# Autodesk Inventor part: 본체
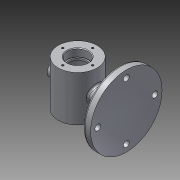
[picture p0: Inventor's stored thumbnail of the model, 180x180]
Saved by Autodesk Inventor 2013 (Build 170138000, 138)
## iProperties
Created: 2018-12
Part Number: 본체
Material: 알루미늄 6061
Document SubType Name: Modeling
Designer: hana-cad23
Density: 2.71 g/cm^3
Mass: 687.624 g
Surface Area: 556.836 cm^2
Volume: 253.736 cm^3
Author: hana-cad23
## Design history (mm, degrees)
sketch "스케치1"
  geometry: L1 (0, 0)-(0, -70); L2 (0, 0)-(30, 0); L3 (30, 0)-(30, -70); L4 (30, -70)-(0, -70); L5 (16, 0)-(16, -12); L6 (16, -12)-(14, -12); L7 (14, -12)-(14, -15); L8 (14, -15)-(25, -15); L9 (25, -15)-(25, -55); L10 (25, -55)-(14, -55); L11 (14, -55)-(14, -58); L12 (14, -58)-(16, -58); L13 (16, -58)-(16, -70)
  constraints: 26 end point, 5 parallel, 4 perpendicular, 2 point on line, 2 vertical, 1 collinear
  dimensions: "d0" = 70 distance of L1.start L1.end; "d1" = 60 diameter of L3 L1; "d2" = 32 diameter of L5 L1; "d3" = 12 distance of L5.start L5.end; "d4" = 28 diameter of L7 L1; "d5" = 3 distance of L6.end L7.end; "d6" = 50 diameter of L9 L1; "d7" = 40 distance of L8.end L9.end; "d8" = 3 distance of L10.end L11.end; "d9" = 28 diameter of L11 L1; "d10" = 32 diameter of L13 L1
revolve "회전1" sketch "스케치1" stored, may be unused: angle "d11" = 90 deg
chamfer "모따기1" distance "d12" = 1; stored, may be unused: second distance "d13" = 2, angle "d14" = 45 deg
chamfer "모따기2" distance "d15" = 1; stored, may be unused: second distance "d16" = 2, angle "d17" = 45 deg
fillet "모깎기1" dims "d18" = 0.3
fillet "모깎기2" dims "d19" = 3
sketch "스케치2" dims "d20" = 46
  geometry: C1 r 17 at (0, 0) reference; C2 r 1.667 at (0, 23); 1 further point
  constraints: 1 centre point, 1 coincident, 1 vertical alignment, 2 other
hole "구멍1" sketch "스케치2" at (0, 23) diameter "d22" = 3.242; stored, may be unused: countersink angle "d26" = 90 deg, drill point angle "d28" = 118 deg; dims "d23" = 8, "d24" = 4, "d25" = 2, "d27" = 10
node "작업 평면1"
node "작업 평면2"
sketch "스케치3"
  geometry: L1 (-30, -70)-(30, -70) reference; L2 (-30, 0)-(30, 0) reference; L3 (0, 0)-(0, -70); C1 r 55 at (0, -35)
  constraints: 2 end point, 2 midpoint, 1 centre point
  dimensions: "d33" = 110 diameter of C1
extrude "돌출1" join sketch "스케치3" distance "d35" = 11; taper "d36" = 0 deg
sketch "스케치4"
  geometry: L1 (-64, -90)-(-64, 20) reference; L2 (-64, -35)-(-49.263, -35); L3 (-64, 20)-(-49.263, -35); L4 (-75, 20)-(-64, 20) reference; 1 further point
  constraints: 4 end point, 1 midpoint, 1 perpendicular
revolve "회전2" sketch "스케치4" stored, may be unused: angle "d43" = 90 deg
node "작업 평면3"
sketch "스케치5"
  geometry: L1 (-30, -35)-(30, -35) reference; L2 (-30, 35)-(30, 35) reference; L3 (0, 35)-(0, -35); C1 r 12 at (0, 0)
  constraints: 2 end point, 2 midpoint, 1 centre point
  dimensions: "d44" = 24 diameter of C1
extrude "돌출2" join sketch "스케치5" distance "d46" = 32.25; taper "d47" = 0 deg; dims "d48" = 3, "d49" = 0
sketch "스케치7" dims "d50" = 88
  geometry: C1 r 55 at (0, 0) reference; C2 r 4.5 at (-44, 0); 2 further points
  constraints: 1 centre point, 1 coincident, 1 horizontal alignment, 2 other
  dimensions: "d52" = 9 diameter of C2
extrude "돌출3" cut sketch "스케치7" distance "d53" = 10; taper "d54" = 0 deg
sketch "스케치8"
  geometry: C1 r 4.5 at (0, 0) reference; C2 r 7 at (0, 0); 1 further point
  constraints: 1 centre point, 1 coincident
  dimensions: "d55" = 14 diameter of C2
extrude "돌출4" cut sketch "스케치8" distance "d57" = 16.75; taper "d58" = 0 deg
sketch "스케치9"
  geometry: C1 r 4.5 at (-44, 0) reference; C2 r 55 at (0, 0) reference; C3 r 4.5 at (0, -44); C4 r 4.5 at (0, 44); C5 r 4.5 at (44, 0); A1 r 44 centre (0, 0) between (-44, 0) and (0, -44); 1 further point
  constraints: 4 centre point, 4 point on circle, 1 coincident
  dimensions: "d65" = 9 diameter of C3; "d66" = 9 diameter of C4; "d67" = 9 diameter of C5
extrude "돌출5" cut sketch "스케치9" distance "d68" = 10; taper "d69" = 0 deg
fillet "모깎기3" dims "d76" = 3
fillet "모깎기4" dims "d77" = 3
fillet "모깎기5" dims "d78" = 3
node "작업 평면4"
sketch "스케치11"
  geometry: L1 (-30, 35)-(30, 35) reference; L2 (-30, -35)-(30, -35) reference; L3 (0, 35)-(0, -35); C1 r 10 at (0, 0); 1 further point
  constraints: 2 end point, 2 midpoint, 1 centre point, 1 other
  dimensions: "d79" = 20 diameter of C1
extrude "돌출7" join sketch "스케치11" distance "d80" = 7; taper "d81" = 0 deg; dims "d89" = 3.5, "d90" = 0
sketch "스케치12"
  geometry: C1 r 10 at (0, 0) reference; C2 r 5 at (0, 0); 1 further point
  constraints: 1 centre point, 1 coincident
  dimensions: "d82" = 10 diameter of C2
extrude "돌출8" cut sketch "스케치12" distance "d84" = 28; taper "d85" = 0 deg
chamfer "모따기3" distance "d86" = 1; stored, may be unused: second distance "d87" = 2, angle "d88" = 45 deg
fillet "모깎기6" dims "d91" = 3
node "작업 평면5"
sketch "스케치13"
  geometry: L1 (-30, 35)-(30, 35) reference; 2 further points
  constraints: 1 other
  dimensions: "d92" = 35 distance from line of L1 point (0, 0); "d93" = 0 horizontal distance of point (0, 35) point (0, 0)
feature "엠보싱1" sketch "스케치13" dims "d0" = 70, "d1" = 60, "d2" = 32, "d3" = 12, "d4" = 28, "d5" = 3, "d6" = 50, "d7" = 40, "d8" = 3, "d9" = 28, "d10" = 32, "d96" = 0.5, "d97" = 0
node "솔리드1"
pattern_circular "원형 패턴1" dims angle "d30" = 360 deg
mirror "대칭1"
pattern_circular "원형 패턴4" dims angle "d74" = 360 deg
node "투영된 루프1"
node "투영된 루프2"
node "투영된 루프3"
other parameters: "d32" = 75
